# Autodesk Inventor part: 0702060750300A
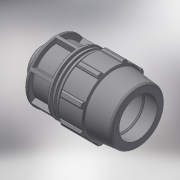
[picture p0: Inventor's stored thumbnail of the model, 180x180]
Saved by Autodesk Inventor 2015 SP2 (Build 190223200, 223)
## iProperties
Created: 2017-02
Part Number: 0702060750300A
Material: Generic
Description: PLASSON MALE ADAPTOR 75-3"
Document SubType Name: Modeling
Designer: KIM
Mass: 964.158 g
Surface Area: 1468.9 cm^2
Volume: 964.158 cm^3
Density: 1 g/cm^3
Appearance: Default
Author: KIM
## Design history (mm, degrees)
derived "87020.ipt"
feature "Solid1::87020.ipt"
tag "TaggingFeature1"
body "Solid1"
other parameters: "d2" = 75, "d4" = 27.85714, "d5" = 48.75, "d7" = 132, "d8" = 99, "d9" = 27.85714, "d11" = 5.57143, "d12" = 105.6, "d13" = 120 deg, "d14" = 97.5, "d15" = 6 deg, "d16" = 118.8, "d18" = 3.75, "d19" = 35 deg, "d20" = 17.5 deg, "d21" = 122.76, "d23" = 0, "d25" = 360 deg, "d27" = 2.64, "d34" = 6.6, "d36" = 0, "d42" = 48.75, "d43" = 3.96, "d46" = 2.25, "d51" = 195, "d52" = 33, "d53" = 1.5, "d55" = 360 deg, "d57" = 87.884, "d58" = 61.5188, "d59" = 39, "d61" = 116.424, "d62" = 2.87143, "d63" = 2.87143, "d66" = 5.74286, "d_" = 75, "E_" = 132, "H_" = 195, "l_2" = 33, "R_" = 87.884, "d60" = 14.35714
